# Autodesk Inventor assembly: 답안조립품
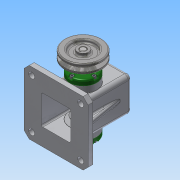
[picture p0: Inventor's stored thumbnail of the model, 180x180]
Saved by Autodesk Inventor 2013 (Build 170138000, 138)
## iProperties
Created: 2016-02
Part Number: 답안조립품
Document SubType Name: Assembly
Designer: Administrator
Author: Administrator
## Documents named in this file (16)
- C:\Users\Administrator\Desktop\460212V1020\답안조립품.iam
- C:\Users\Administrator\Desktop\460212V1020\본체.ipt
- C:\Users\Administrator\Desktop\460212V1020\V벨트풀리.ipt
- C:\Users\Administrator\Desktop\460212V1020\고정핀 1.2 x 10.ipt
- C:\Users\Administrator\Desktop\460212V1020\뒤커버.ipt
- C:\Users\Administrator\Desktop\460212V1020\링크.ipt
- C:\Users\Administrator\Desktop\460212V1020\멈춤나사 M3x8.ipt
- C:\Users\Administrator\Desktop\460212V1020\베어링 12 x 32 x 10.ipt
- C:\Users\Administrator\Desktop\460212V1020\볼트 M4 x 12.ipt
- C:\Users\Administrator\Desktop\460212V1020\부시.ipt
- C:\Users\Administrator\Desktop\460212V1020\슬라이드.ipt
- C:\Users\Administrator\Desktop\460212V1020\앞커버.ipt
- C:\Users\Administrator\Desktop\460212V1020\오일실 12 25 7.ipt
- C:\Users\Administrator\Desktop\460212V1020\키 4 x 4 x 10.ipt
- C:\Users\Administrator\Desktop\460212V1020\편심축.ipt
- C:\Users\Administrator\Desktop\460212V1020\핀 5 x 18.ipt
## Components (11 placed, 4 different names)
1. V벨트풀리:1
2. 고정핀 1.2 x 10:1 — 각도:1
3. 핀 5 x 18:1 — 각도:1
4. ISO 4762 M4 x 12:2
5. ISO 4762 M4 x 12:1
6. ISO 4762 M4 x 12:3
7. ISO 4762 M4 x 12:4
8. ISO 4762 M4 x 12:5
9. ISO 4762 M4 x 12:6
10. ISO 4762 M4 x 12:7
11. ISO 4762 M4 x 12:8
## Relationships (1: Angle 1)
- 각도:1 [Angle]: 고정핀 1.2 x 10:1 ↔ 핀 5 x 18:1
